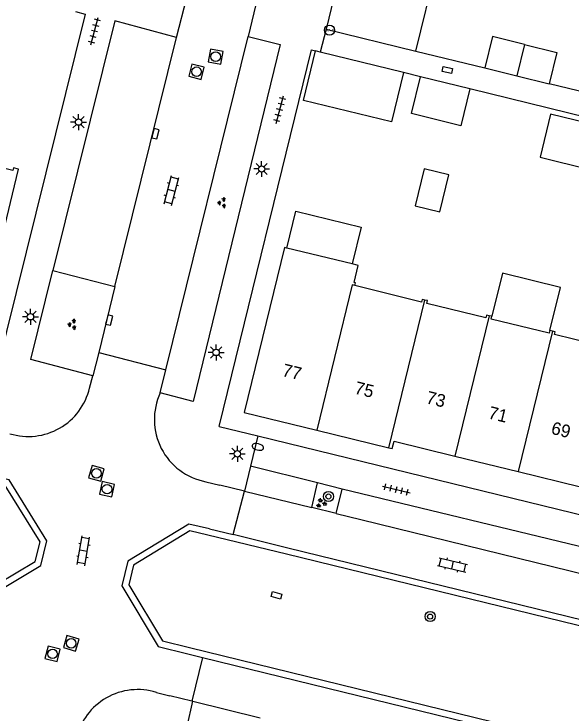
# Model space of a CAD drawing. Extents: x 125000 to 129004, y 397500 to 399008.
# Drawn here: x 126314.6 to 126358.5, y 398273.2 to 398328.3 of the extents above; entities that cross this region are included whole.
import ezdxf

# ---------------------------------------------------------------- set-up
doc = ezdxf.new("R2010")
doc.units = 0
for name, color, linetype in [('gg-afsc-erfafscheiding', 7, 'Continuous'), ('gg-afsc-muur', 7, 'Continuous'), ('gg-anno-huisnummerreeks BGT', 7, 'Continuous'), ('gg-bbg-bijgebouw', 7, 'Continuous'), ('gg-bbg-gedigitaliseerde bijgebouw', 7, 'Continuous'), ('gg-bbg-hoofdgebouw', 7, 'Continuous'), ('gg-bbg-luifel en loopbrug', 7, 'Continuous'), ('gg-bbg-tussenscheiding', 7, 'Continuous'), ('gg-knt-verharding', 7, 'Continuous'), ('gg-knt-verharding nz', 7, 'Continuous'), ('gt-grn-weggrens', 7, 'Continuous'), ('gt-symb-boom', 7, 'Continuous'), ('gt-symb-brandkraan', 7, 'Continuous'), ('gt-symb-groenvak', 7, 'Continuous'), ('gt-symb-hoogtemerk', 7, 'Continuous'), ('gt-symb-klinker verharding', 7, 'Continuous'), ('gt-symb-kolk', 7, 'Continuous'), ('gt-symb-kolk center center', 7, 'Continuous'), ('gt-symb-lichtmast', 7, 'Continuous'), ('gt-symb-rioolschacht', 7, 'Continuous'), ('gt-symb-tegel verharding', 7, 'Continuous')]:
    doc.layers.add(name, color=color, linetype=linetype)

# ---------------------------------------------------------------- blocks, each defined once
blk = doc.blocks.new('gt0-KOLKCC')
at = {"layer": 'gt-symb-kolk center center'}
blk.add_lwpolyline([(-0.375, 0.2), (0.375, 0.2), (0.375, -0.2), (-0.375, -0.2)], close=True, dxfattribs=at)
blk = doc.blocks.new('gt0-KL1')
at = {"layer": 'gt-symb-klinker verharding'}
for p, q in [((-1.15, 0.3), (1.15, 0.3)), ((-1, -0.3), (-1, 0.3)), ((-0.5, 0.3), (-0.5, 0.45)), ((0, -0.3), (0, 0.3)), ((0.5, 0.3), (0.5, 0.45)), ((1, -0.3), (1, 0.3)), ((-1.15, -0.3), (1.15, -0.3)), ((-0.5, -0.45), (-0.5, -0.3)), ((0.5, -0.45), (0.5, -0.3))]:
    blk.add_line(p, q, dxfattribs=at)
blk = doc.blocks.new('gt0-BOOM')
at = {"layer": 'gt-symb-boom'}
for radius in [0.4, 0.2]:
    blk.add_circle((0, 0), radius, dxfattribs=at)
blk = doc.blocks.new('gt0-GRVAK')
at = {"layer": 'gt-symb-groenvak'}
for p, q in [((-0.11, 0.189), (-0.228, 0.24)), ((-0.182, 0.153), (0.088, 0.153)), ((-0.091, 0.211), (-0.156, 0.322)), ((-0.047, 0.214), (-0.047, 0.393)), ((-0.004, 0.211), (0.061, 0.322)), ((0.015, 0.189), (0.133, 0.24)), ((0.262, -0.052), (0.197, 0.059)), ((0.305, -0.049), (0.305, 0.13)), ((0.349, -0.052), (0.414, 0.059)), ((-0.245, -0.228), (-0.363, -0.177)), ((-0.318, -0.264), (-0.047, -0.264)), ((-0.226, -0.206), (-0.291, -0.095)), ((-0.183, -0.203), (-0.183, -0.024)), ((-0.139, -0.206), (-0.074, -0.095)), ((-0.12, -0.228), (-0.002, -0.177)), ((0.243, -0.074), (0.125, -0.023)), ((0.17, -0.11), (0.441, -0.11)), ((0.368, -0.074), (0.486, -0.023))]:
    blk.add_line(p, q, dxfattribs=at)
blk = doc.blocks.new('gt0-TEG1')
at = {"layer": 'gt-symb-tegel verharding'}
for p, q in [((-1.125, 0), (1.125, 0)), ((-0.9, -0.25), (-0.9, 0.25)), ((-0.45, -0.25), (-0.45, 0.25)), ((0, -0.25), (0, 0.25)), ((0.45, -0.25), (0.45, 0.25)), ((0.9, -0.25), (0.9, 0.25))]:
    blk.add_line(p, q, dxfattribs=at)
blk = doc.blocks.new('gt0-RS')
at = {"layer": 'gt-symb-rioolschacht'}
blk.add_lwpolyline([(-0.5, -0.5), (0.5, -0.5), (0.5, 0.5), (-0.5, 0.5)], close=True, dxfattribs=at)
blk.add_circle((0, 0), 0.375, dxfattribs=at)
blk = doc.blocks.new('gt0-HMERK')
at = {"layer": 'gt-symb-hoogtemerk'}
blk.add_circle((0, 0), 0.4, dxfattribs=at)
blk.add_text('N.A.P', height=0.2, dxfattribs=at).set_placement((-0.354, -0.1))
blk = doc.blocks.new('gt0-LMAST')
at = {"layer": 'gt-symb-lichtmast'}
for p, q in [((-0.005, 0.246), (-0.005, 0.621)), ((-0.182, 0.173), (-0.447, 0.438)), ((0.172, 0.173), (0.437, 0.438)), ((-0.255, -0.004), (-0.63, -0.004)), ((-0.182, -0.181), (-0.447, -0.446)), ((-0.005, -0.254), (-0.005, -0.629)), ((0.437, -0.446), (0.172, -0.181)), ((0.245, -0.004), (0.62, -0.004))]:
    blk.add_line(p, q, dxfattribs=at)
blk.add_circle((-0.005, -0.004), 0.25, dxfattribs=at)
blk = doc.blocks.new('gt0-BR')
at = {"layer": 'gt-symb-brandkraan'}
for centre, radius, start, end in [((-0.244, 0), 0.206, 107.5669, 252.4331), ((0.599, -2.664), 3, 106.892, 107.5669), ((0, -0.691), 0.938, 73.108, 106.892), ((-0.599, -2.664), 3, 72.4331, 73.108), ((0.244, 0), 0.206, 287.567, 72.4331), ((0.599, 2.664), 3, 252.4331, 253.108), ((0, 0.691), 0.938, 253.108, 286.8921), ((-0.599, 2.664), 3, 286.8921, 287.567)]:
    blk.add_arc(centre, radius, start, end, dxfattribs=at)
blk = doc.blocks.new('gt0-KOLK')
at = {"layer": 'gt-symb-kolk'}
blk.add_lwpolyline([(0, 0), (0.375, 0), (0.375, 0.4), (-0.375, 0.4), (-0.375, 0), (0, 0)], dxfattribs=at)

msp = doc.modelspace()

# ---------------------------------------------------------------- linework, layer by layer
at = {"layer": 'gg-afsc-erfafscheiding'}
for p, q in [((126346.305, 398325.324), (126351.723, 398324.011)), ((126346.672, 398323.316), (126345.326, 398323.647)), ((126362.216, 398321.443), (126356.801, 398322.762)), ((126368.494, 398317.956), (126350.556, 398322.362))]:
    msp.add_line(p, q, dxfattribs=at)
at = {"layer": 'gg-afsc-muur'}
for points in [[(126319.449, 398328.466), (126320.233, 398328.246), (126313.192, 398300.038)], [(126330.797, 398295.746), (126338.069, 398325.431), (126338.378, 398325.352)]]:
    msp.add_lwpolyline(points, dxfattribs=at)
at = {"layer": 'gg-bbg-bijgebouw'}
for p, q in [((126351.723, 398324.011), (126354.262, 398323.387)), ((126354.262, 398323.387), (126356.801, 398322.762))]:
    msp.add_line(p, q, dxfattribs=at)
for points in [[(126354.869, 398325.853), (126352.33, 398326.477), (126351.723, 398324.011)], [(126354.869, 398325.853), (126357.408, 398325.228), (126356.801, 398322.762)]]:
    msp.add_lwpolyline(points, dxfattribs=at)
at = {"layer": 'gg-bbg-gedigitaliseerde bijgebouw'}
for p, q in [((126338.762, 398325.259), (126338.378, 398325.352)), ((126345.326, 398323.647), (126338.762, 398325.259)), ((126350.556, 398322.362), (126346.672, 398323.316))]:
    msp.add_line(p, q, dxfattribs=at)
for points in [[(126345.326, 398323.647), (126344.389, 398319.758), (126337.434, 398321.435), (126338.378, 398325.352)], [(126350.556, 398322.362), (126349.845, 398319.453), (126345.959, 398320.404), (126346.672, 398323.316)], [(126360.813, 398319.409), (126356.923, 398320.361), (126356.091, 398316.961), (126360.011, 398316.002)]]:
    msp.add_lwpolyline(points, dxfattribs=at)
at = {"layer": 'gg-bbg-hoofdgebouw'}
for p, q in [((126340.671, 398332.965), (126339.218, 398327.052)), ((126339.218, 398327.052), (126346.305, 398325.324)), ((126341.286, 398308.559), (126336.133, 398309.8)), ((126341.666, 398308.467), (126341.286, 398308.559)), ((126352.285, 398304.426), (126352.081, 398304.476)), ((126357.073, 398303.254), (126356.869, 398303.305)), ((126338.484, 398295.456), (126344.165, 398294.067)), ((126349.37, 398293.412), (126354.367, 398292.19)), ((126354.367, 398292.19), (126359.291, 398290.986))]:
    msp.add_line(p, q, dxfattribs=at)
for points in [[(126346.305, 398325.324), (126347.905, 398331.886), (126344.534, 398332.708), (126345.702, 398337.398)], [(126304.427, 398311.646), (126307.377, 398310.924), (126305.563, 398303.508), (126308.548, 398302.796), (126308.383, 398302.106), (126312.052, 398301.208), (126312.993, 398304.888), (126312.305, 398305.064), (126314.974, 398316.033), (126314.565, 398316.137), (126314.513, 398315.933), (126309.256, 398317.206), (126309.834, 398319.546), (126306.54, 398320.346)], [(126336.133, 398309.8), (126335.939, 398309.847), (126332.765, 398296.854), (126338.484, 398295.456)], [(126341.483, 398306.848), (126341.533, 398307.062), (126341.432, 398307.086), (126341.759, 398308.445), (126341.666, 398308.467)], [(126347.014, 398305.713), (126346.805, 398305.764), (126346.752, 398305.55), (126341.483, 398306.848)], [(126352.081, 398304.476), (126351.877, 398304.526), (126351.825, 398304.312), (126347.171, 398305.448), (126347.223, 398305.661), (126347.014, 398305.713)], [(126356.869, 398303.305), (126356.816, 398303.092), (126352.233, 398304.213), (126352.285, 398304.426)], [(126361.998, 398302.049), (126361.78, 398302.103), (126361.728, 398301.893), (126357.227, 398303.003), (126357.277, 398303.203), (126357.073, 398303.254)], [(126344.165, 398294.067), (126344.436, 398294.001), (126344.578, 398294.584), (126349.37, 398293.412)]]:
    msp.add_lwpolyline(points, dxfattribs=at)
at = {"layer": 'gg-bbg-luifel en loopbrug'}
for points in [[(126348.894, 398315.568), (126346.951, 398316.043), (126346.239, 398313.129), (126348.181, 398312.654), (126348.894, 398315.568)], [(126336.133, 398309.8), (126336.846, 398312.714), (126341.992, 398311.444), (126341.286, 398308.559)], [(126356.869, 398303.305), (126357.701, 398306.705), (126353.117, 398307.826), (126352.285, 398304.426)]]:
    msp.add_lwpolyline(points, dxfattribs=at)
at = {"layer": 'gg-bbg-tussenscheiding'}
for p, q in [((126354.869, 398325.853), (126354.262, 398323.387)), ((126344.165, 398294.067), (126347.014, 398305.713)), ((126352.081, 398304.476), (126349.37, 398293.412)), ((126357.073, 398303.254), (126354.367, 398292.19))]:
    msp.add_line(p, q, dxfattribs=at)
msp.add_lwpolyline([(126341.483, 398306.848), (126341.282, 398306.897), (126338.484, 398295.456)], dxfattribs=at)
at = {"layer": 'gg-knt-verharding'}
for p, q in [((126335.132, 398334.888), (126333.065, 398326.495)), ((126327.429, 398326.407), (126329.054, 398332.864)), ((126326.584, 398300.22), (126333.065, 398326.495)), ((126317.683, 398308.036), (126322.557, 398306.788)), ((126322.557, 398306.788), (126321.3, 398301.565)), ((126321.3, 398301.565), (126320.826, 398299.742)), ((126321.3, 398301.565), (126326.584, 398300.22)), ((126326.145, 398298.394), (126326.584, 398300.22)), ((126320.573, 398298.768), (126320.826, 398299.742)), ((126330.797, 398295.746), (126333.839, 398295.002)), ((126333.839, 398295.002), (126432.346, 398270.92)), ((126333.253, 398292.602), (126332.791, 398290.635)), ((126338.545, 398291.294), (126333.253, 398292.602)), ((126329.734, 398291.386), (126330.851, 398291.105)), ((126332.791, 398290.635), (126330.851, 398291.105)), ((126338.086, 398289.363), (126338.545, 398291.294)), ((126340.495, 398290.812), (126338.545, 398291.294)), ((126331.881, 398287.232), (126332.791, 398290.635)), ((126340.008, 398288.894), (126340.495, 398290.812)), ((126360.397, 398285.986), (126340.495, 398290.812)), ((126340.008, 398288.894), (126338.086, 398289.363)), ((126330.023, 398287.661), (126331.881, 398287.232)), ((126328.318, 398277.823), (126329.473, 398277.528)), ((126328.44, 398278.308), (126430.454, 398253.401)), ((126329.473, 398277.528), (126328.634, 398274.094)), ((126329.473, 398277.528), (126420.97, 398255.202)), ((126325.838, 398274.783), (126326.899, 398274.519)), ((126328.634, 398274.094), (126326.899, 398274.519)), ((126328.265, 398272.094), (126328.713, 398274.075)), ((126328.713, 398274.075), (126328.634, 398274.094))]:
    msp.add_line(p, q, dxfattribs=at)
for points in [[(126327.429, 398326.407), (126322.565, 398327.716), (126317.683, 398308.036)], [(126333.065, 398326.495), (126335.602, 398325.867), (126328.73, 398297.707), (126326.145, 398298.394)], [(126320.826, 398299.742), (126315.925, 398301.022), (126317.683, 398308.036)], [(126310.481, 398282.19), (126311.85, 398281.876), (126316.723, 398284.77), (126317.204, 398286.721), (126314.226, 398291.523), (126312.846, 398291.817)], [(126310.6, 398282.676), (126311.767, 398282.408), (126316.288, 398285.093), (126316.668, 398286.636), (126313.913, 398291.078), (126312.727, 398291.331)], [(126330.023, 398287.661), (126328.403, 398288.052), (126323.593, 398285.128), (126323.121, 398283.174), (126325.989, 398278.409), (126328.318, 398277.823)], [(126329.906, 398287.175), (126328.486, 398287.518), (126324.03, 398284.809), (126323.655, 398283.256), (126326.311, 398278.844), (126328.44, 398278.308)], [(126432.617, 398262.065), (126336.086, 398285.673), (126329.906, 398287.175)], [(126423.334, 398264.85), (126336.206, 398286.158), (126331.881, 398287.232)]]:
    msp.add_lwpolyline(points, dxfattribs=at)
for centre, radius, start, end in [((126315.74, 398299.924), 4.969, 253.0888, 346.5463), ((126330.667, 398296.287), 4.989, 155.0163, 259.2203), ((126324.376, 398270.01), 4.992, 72.9692, 166.5049)]:
    msp.add_arc(centre, radius, start, end, dxfattribs=at)
at = {"layer": 'gg-knt-verharding nz'}
for p, q in [((126322.557, 398306.788), (126327.429, 398326.407)), ((126332.791, 398290.635), (126338.086, 398289.363)), ((126340.008, 398288.894), (126341.953, 398288.406)), ((126341.953, 398288.406), (126359.904, 398284.007)), ((126328.713, 398274.075), (126334.017, 398272.77))]:
    msp.add_line(p, q, dxfattribs=at)
at = {"layer": 'gt-grn-weggrens'}
for p, q in [((126339.218, 398327.052), (126338.762, 398325.259)), ((126333.839, 398295.002), (126333.253, 398292.602))]:
    msp.add_line(p, q, dxfattribs=at)

# ---------------------------------------------------------------- block references
at = {"layer": 'gt-symb-boom'}
for p in [(126339.403, 398290.221), (126347.419, 398280.755)]:
    msp.add_blockref('gt0-BOOM', p, dxfattribs=at)
at = {"layer": 'gt-symb-brandkraan', "rotation": -14.064036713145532}
msp.add_blockref('gt0-BR', (126333.837, 398294.134), dxfattribs=at)
at = {"layer": 'gt-symb-groenvak', "rotation": 75.2272760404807}
for p in [(126331.047, 398313.353), (126319.233, 398303.761)]:
    msp.add_blockref('gt0-GRVAK', p, dxfattribs=at)
at = {"layer": 'gt-symb-groenvak'}
msp.add_blockref('gt0-GRVAK', (126338.823, 398289.687), dxfattribs=at)
at = {"layer": 'gt-symb-hoogtemerk'}
msp.add_blockref('gt0-HMERK', (126339.49, 398326.986), dxfattribs=at)
at = {"layer": 'gt-symb-klinker verharding'}
for p, rotation in [((126327.026, 398314.343), 75.2272760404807), ((126320.087, 398285.943), 80.44347238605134), ((126349.189, 398284.822), -13.174926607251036)]:
    msp.add_blockref('gt0-KL1', p, dxfattribs=dict(at, rotation=rotation))
at = {"layer": 'gt-symb-kolk'}
for p, rotation in [((126325.565, 398318.874), -104.00844348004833), ((126321.926, 398304.177), -103.59156043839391)]:
    msp.add_blockref('gt0-KOLK', p, dxfattribs=dict(at, rotation=rotation))
at = {"layer": 'gt-symb-kolk center center'}
for p, rotation in [((126348.783, 398323.842), 167.9932916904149), ((126335.309, 398282.43), 164.4482750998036)]:
    msp.add_blockref('gt0-KOLKCC', p, dxfattribs=dict(at, rotation=rotation))
at = {"layer": 'gt-symb-lichtmast'}
for p in [(126319.708, 398319.742), (126334.142, 398316.047), (126315.915, 398304.392), (126330.553, 398301.583), (126332.227, 398293.59)]:
    msp.add_blockref('gt0-LMAST', p, dxfattribs=at)
at = {"layer": 'gt-symb-rioolschacht'}
for p, rotation in [((126330.513, 398324.898), -100.95043426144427), ((126329.009, 398323.711), -104.06403671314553), ((126321.107, 398292.049), 74.156917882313), ((126321.947, 398290.8), 77.58922528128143), ((126319.122, 398278.646), 73.79481462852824), ((126317.654, 398277.817), -14.175142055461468)]:
    msp.add_blockref('gt0-RS', p, dxfattribs=dict(at, rotation=rotation))
at = {"layer": 'gt-symb-tegel verharding'}
for p, rotation in [((126320.965, 398326.906), 75.2272760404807), ((126335.562, 398320.717), 75.2272760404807), ((126344.755, 398290.774), -13.702889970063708)]:
    msp.add_blockref('gt0-TEG1', p, dxfattribs=dict(at, rotation=rotation))

# ---------------------------------------------------------------- texts
at = {"layer": 'gg-anno-huisnummerreeks BGT'}
for s, rotation, p in [('77', 346.3, (126335.699, 398299.739)), ('75', 346.2, (126341.399, 398298.346)), ('73', 346.2, (126347.048, 398297.583)), ('71', 346.2, (126351.943, 398296.386)), ('69', 346.2, (126356.903, 398295.173))]:
    msp.add_text(s, height=1, rotation=rotation, dxfattribs=at).set_placement(p)

doc.saveas('drawing.dxf')
